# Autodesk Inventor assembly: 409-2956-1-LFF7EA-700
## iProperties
Created: 2010-06
Part Number: 409-2956-1-LFF7EA-700
Document SubType Name: Assembly
Designer: S. Boerckel
Mass: 3.18924e+06 g
Surface Area: 810796 cm^2
Volume: 421021 cm^3
Density: 7.57501 g/cm^3
Description: MECHANICAL
Material: ASSEMBLY
Author: S. Boerckel
Revision Number: B
Title: MECHANICAL
Subject: LIQUID FUEL FORWARDING PUMP SKID-7EA
